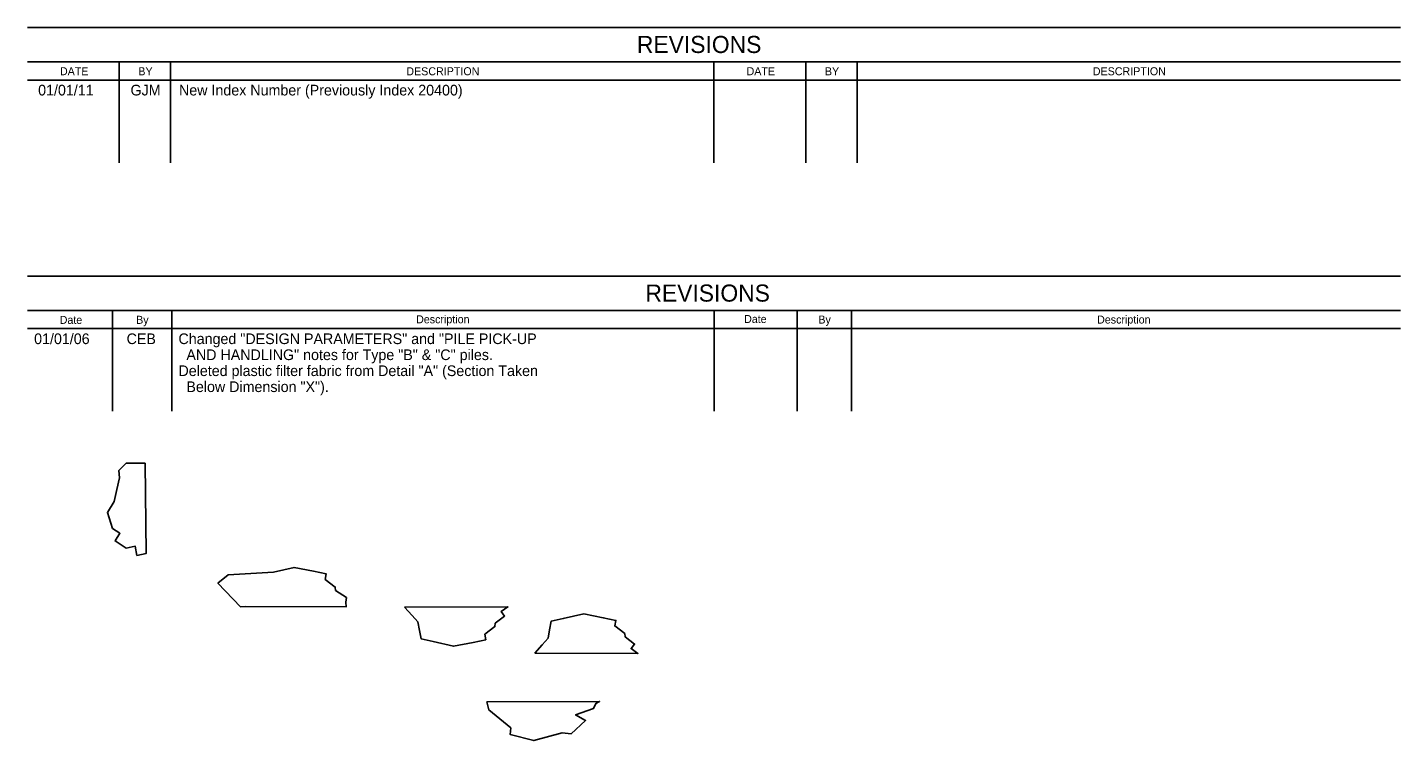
# Model space of a CAD drawing. Extents: x 111162.5 to 111216.6, y 110741.1 to 110776.1.
# Drawn here: x 111162.54 to 111178, y 110741.14 to 110749.17 of the extents above; entities that cross this region are included whole.
import ezdxf

# ---------------------------------------------------------------- set-up
doc = ezdxf.new("R2010")
doc.units = 0
for name, color, linetype in [('Border', 7, 'Continuous'), ('Patterning', 7, 'Continuous'), ('SheetBorder_dp', 7, 'Continuous')]:
    doc.layers.add(name, color=color, linetype=linetype)

msp = doc.modelspace()

# ---------------------------------------------------------------- linework, layer by layer
at = {"layer": 'Border'}
for p, q in [((111177.998, 110749.173), (111162.539, 110749.173)), ((111177.998, 110748.786), (111162.539, 110748.786)), ((111163.571, 110748.786), (111163.571, 110747.65)), ((111164.151, 110748.786), (111164.151, 110747.65)), ((111170.268, 110748.786), (111170.268, 110747.65)), ((111171.301, 110748.786), (111171.301, 110747.65)), ((111171.881, 110748.786), (111171.881, 110747.65)), ((111162.539, 110748.581), (111177.998, 110748.581)), ((111177.998, 110746.373), (111162.54, 110746.373)), ((111177.998, 110745.987), (111162.54, 110745.987)), ((111163.496, 110745.987), (111163.496, 110744.851)), ((111164.165, 110745.987), (111164.165, 110744.851)), ((111170.269, 110745.987), (111170.269, 110744.851)), ((111171.203, 110745.987), (111171.203, 110744.851)), ((111171.815, 110745.987), (111171.815, 110744.851)), ((111162.54, 110745.782), (111177.998, 110745.782))]:
    msp.add_line(p, q, dxfattribs=at)
at = {"layer": 'Patterning'}
for points in [[(111163.863, 110744.266), (111163.649, 110744.266), (111163.568, 110744.184), (111163.576, 110744.103), (111163.546, 110743.97), (111163.516, 110743.837), (111163.439, 110743.713), (111163.495, 110743.533), (111163.58, 110743.478), (111163.525, 110743.392), (111163.649, 110743.311), (111163.752, 110743.332), (111163.772, 110743.229), (111163.875, 110743.249)], [(111164.989, 110742.652), (111164.936, 110742.651), (111164.936, 110742.651), (111164.684, 110742.915), (111164.798, 110743.01), (111165.31, 110743.041), (111165.541, 110743.094), (111165.76, 110743.05), (111165.903, 110743.021), (111165.89, 110742.958), (111166.004, 110742.872), (111166.008, 110742.834), (111166.129, 110742.754), (111166.123, 110742.703), (111166.128, 110742.651)], [(111166.785, 110742.648), (111166.869, 110742.554), (111166.935, 110742.48), (111166.952, 110742.385), (111166.97, 110742.29), (111167.107, 110742.258), (111167.337, 110742.206), (111167.556, 110742.25), (111167.699, 110742.279), (111167.687, 110742.342), (111167.801, 110742.428), (111167.805, 110742.466), (111167.91, 110742.545), (111167.871, 110742.597), (111167.948, 110742.65)], [(111168.25, 110742.129), (111168.333, 110742.223), (111168.4, 110742.297), (111168.417, 110742.392), (111168.434, 110742.487), (111168.571, 110742.518), (111168.802, 110742.571), (111169.021, 110742.527), (111169.164, 110742.498), (111169.151, 110742.435), (111169.265, 110742.349), (111169.269, 110742.311), (111169.374, 110742.231), (111169.335, 110742.18), (111169.412, 110742.126)], [(111167.712, 110741.582), (111167.734, 110741.49), (111167.939, 110741.32), (111167.982, 110741.286), (111167.973, 110741.213), (111168.239, 110741.145), (111168.558, 110741.23), (111168.659, 110741.222), (111168.822, 110741.372), (111168.71, 110741.434), (111168.912, 110741.505), (111168.937, 110741.562), (111168.98, 110741.586)]]:
    msp.add_lwpolyline(points, close=True, dxfattribs=at)

# ---------------------------------------------------------------- texts
at = {"layer": 'Border'}
for s, height, p in [('REVISIONS', 0.1925, (111169.496, 110746.086)), ('By', 0.0901, (111163.762, 110745.836)), ('By', 0.0901, (111171.443, 110745.839)), ('01/01/06', 0.12, (111162.614, 110745.608)), ('CEB', 0.12, (111163.655, 110745.608)), ('Changed "DESIGN PARAMETERS" and "PILE PICK-UP', 0.12001, (111164.239, 110745.608)), ('  AND HANDLING" notes for Type "B" & "C" piles. ', 0.12001, (111164.239, 110745.428)), ('Deleted plastic filter fabric from Detail "A" (Section Taken', 0.12001, (111164.239, 110745.248)), ('  Below Dimension "X").', 0.12001, (111164.239, 110745.068))]:
    msp.add_text(s, height=height, dxfattribs=at).set_placement(p)
for s, height, rotation, p in [('Date', 0.0897, 359.8693, (111162.902, 110745.836)), ('Description', 0.09004, 0.0498, (111166.914, 110745.842)), ('Date', 0.0897, 359.8693, (111170.607, 110745.846)), ('Description', 0.09004, 0.0498, (111174.581, 110745.839))]:
    msp.add_text(s, height=height, rotation=rotation, dxfattribs=at).set_placement(p)
at = {"layer": 'SheetBorder_dp'}
for s, height, p in [('REVISIONS', 0.1925, (111169.4, 110748.885)), ('BY', 0.0901, (111163.787, 110748.634)), ('BY', 0.0901, (111171.517, 110748.634)), ('01/01/11', 0.12, (111162.659, 110748.407)), ('GJM', 0.12, (111163.699, 110748.407)), ('New Index Number (Previously Index 20400)', 0.12, (111164.245, 110748.407))]:
    msp.add_text(s, height=height, dxfattribs=at).set_placement(p)
for s, height, rotation, p in [('DATE', 0.0897, 359.8693, (111162.905, 110748.635)), ('DESCRIPTION', 0.09005, 0.0498, (111166.804, 110748.634)), ('DATE', 0.0897, 359.8693, (111170.635, 110748.635)), ('DESCRIPTION', 0.09005, 0.0498, (111174.533, 110748.634))]:
    msp.add_text(s, height=height, rotation=rotation, dxfattribs=at).set_placement(p)

doc.saveas('drawing.dxf')
